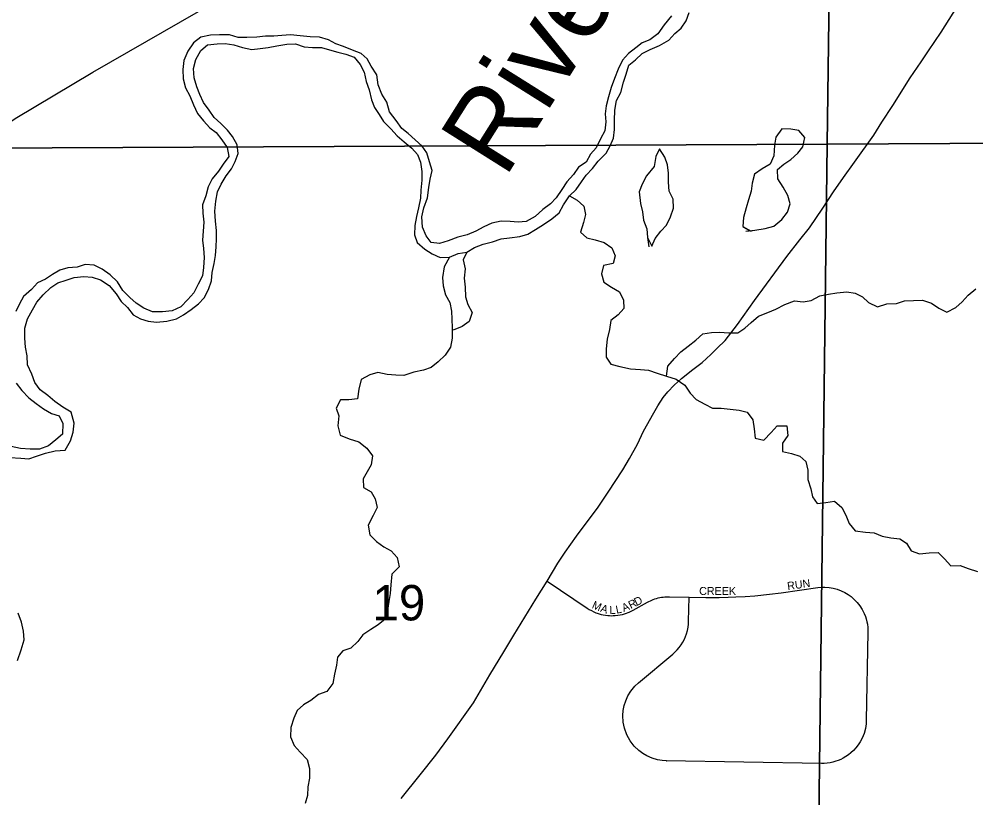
# Model space of a CAD drawing. Extents: x 1857828 to 2277390, y 930619 to 1324581.
# Drawn here: x 2065754 to 2071728, y 1200295 to 1205159 of the extents above; entities that cross this region are included whole.
import ezdxf

# ---------------------------------------------------------------- set-up
doc = ezdxf.new("R2010")
doc.units = 0
for name, color, linetype in [('GM_X_County_Road', 7, 'Continuous'), ('GM_X_Major_River', 7, 'Continuous'), ('GM_X_Major_River_Text', 7, 'Continuous'), ('GM_X_Minor_Lake', 7, 'Continuous'), ('GM_X_Minor_River', 7, 'Continuous'), ('GM_X_Section', 7, 'Continuous'), ('GM_X_Section_Text', 7, 'Continuous'), ('GM_X_Township_Subdivision', 7, 'Continuous'), ('GM_X_Township_Subdivision_Text', 7, 'Continuous'), ('GM_X_US_Route', 7, 'Continuous')]:
    doc.layers.add(name, color=color, linetype=linetype)

msp = doc.modelspace()

# ---------------------------------------------------------------- linework, layer by layer
at = {"layer": 'GM_X_County_Road'}
msp.add_lwpolyline([(2068140.2, 1200292.1), (2068258.8, 1200439.3), (2068355.7, 1200562.4), (2068430.8, 1200663.2), (2068590.7, 1200889), (2068693.1, 1201064.2), (2068779.9, 1201207.2), (2068842.9, 1201312), (2068980.9, 1201535.6), (2069051.9, 1201648.4), (2069118.9, 1201761.2), (2069164.3, 1201829.7), (2069235.3, 1201930.5), (2069369.7, 1202112), (2069432.8, 1202204.6), (2069523.6, 1202343.7), (2069565, 1202414.2), (2069616.1, 1202504.8), (2069653.4, 1202585.3), (2069716.4, 1202700), (2069742, 1202744.3), (2069775.6, 1202796.7), (2069805.2, 1202831), (2069844.8, 1202873.4), (2069890.4, 1202913.9), (2069959.9, 1202970.6), (2070019.5, 1203015.1), (2070073, 1203063.7), (2070112.6, 1203104.1), (2070162.2, 1203152.6), (2070239.3, 1203251.4), (2070345.9, 1203402.6), (2070547.4, 1203676.8), (2070628.4, 1203781.7), (2070689.8, 1203856.4), (2070772.7, 1203979.3), (2070839.7, 1204080), (2070900.9, 1204170.7), (2070970.1, 1204265.5), (2071090.5, 1204434.8), (2071141.8, 1204515.4), (2071208.8, 1204620.2), (2071317.3, 1204793.4), (2071386.4, 1204892.1), (2071431.8, 1204960.7), (2071510.7, 1205077.5), (2071636.9, 1205275)], dxfattribs=at)
at = {"layer": 'GM_X_Major_River'}
for points in [[(2068269, 1204154.3), (2068263.1, 1204090.2), (2068259.3, 1204040.1), (2068247.4, 1203979.9), (2068235.5, 1203925.8), (2068225.6, 1203869.6), (2068223.8, 1203811.5), (2068239.9, 1203763.4), (2068288, 1203723.4), (2068334.1, 1203693.4), (2068384.1, 1203671.4), (2068442.1, 1203673.5), (2068496.1, 1203695.6), (2068550.1, 1203703.7), (2068598, 1203733.8), (2068652, 1203754), (2068709.9, 1203768.1), (2068763.9, 1203786.2), (2068815.9, 1203792.3), (2068879.9, 1203802.4), (2068929.9, 1203816.5), (2068977.8, 1203844.6), (2069027.7, 1203876.8), (2069079.7, 1203912.9), (2069125.6, 1203949.1), (2069153.5, 1203999.2), (2069191.3, 1204055.4), (2069233.3, 1204095.6), (2069265.2, 1204143.7), (2069295.1, 1204183.8), (2069335, 1204226), (2069368.9, 1204272.1), (2069418.8, 1204322.3), (2069444.7, 1204368.5), (2069464.6, 1204416.6), (2069472.4, 1204470.7), (2069472.3, 1204526.9), (2069474.2, 1204591), (2069484, 1204651.2), (2069511.9, 1204701.3), (2069527.8, 1204765.5), (2069543.6, 1204815.6), (2069561.5, 1204871.8), (2069603.4, 1204905.9), (2069645.4, 1204944), (2069695.3, 1204970.2), (2069753.3, 1204994.3), (2069811.2, 1205028.5), (2069849.1, 1205068.6), (2069889, 1205102.7), (2069918.9, 1205148.9), (2069938.8, 1205201)], [(2069826.8, 1205178.8), (2069781, 1205122.6), (2069743.1, 1205068.4), (2069693.2, 1205030.3), (2069645.2, 1205012.2), (2069605.3, 1204980.1), (2069559.3, 1204943.9), (2069521.4, 1204903.8), (2069493.6, 1204847.6), (2069471.7, 1204789.4), (2069451.8, 1204731.3), (2069434, 1204673.1), (2069420.1, 1204617), (2069414.2, 1204566.9), (2069418.3, 1204516.8), (2069410.4, 1204462.6), (2069384.6, 1204412.5), (2069356.7, 1204356.3), (2069322.8, 1204316.2), (2069294.9, 1204266), (2069246.9, 1204233.9)], [(2069246.9, 1204233.9), (2069215, 1204189.8), (2069173.1, 1204143.6), (2069143.2, 1204095.4), (2069107.4, 1204043.3), (2069071.4, 1204005.1), (2069023.5, 1203971), (2068975.6, 1203926.8), (2068919.7, 1203894.7), (2068869.7, 1203890.6), (2068819.7, 1203894.5), (2068763.7, 1203896.4), (2068705.7, 1203884.3), (2068655.7, 1203862.2), (2068605.8, 1203834.1), (2068551.8, 1203812), (2068493.8, 1203797.8), (2068433.9, 1203773.7), (2068379.9, 1203757.6), (2068325.9, 1203763.5), (2068295.8, 1203805.6), (2068273.7, 1203859.7), (2068269.5, 1203923.8), (2068281.4, 1203980), (2068303.3, 1204044.1), (2068313.1, 1204108.3), (2068321, 1204160.4), (2068332.9, 1204214.6), (2068316.7, 1204268.7), (2068300.6, 1204324.8), (2068270.5, 1204366.8), (2068226.4, 1204404.8), (2068184.3, 1204444.9), (2068144.2, 1204476.9), (2068108.1, 1204527), (2068066, 1204581), (2068049.8, 1204641.1), (2068019.7, 1204691.2), (2067995.6, 1204749.3), (2067987.4, 1204811.4), (2067953.3, 1204865.5), (2067927.2, 1204911.6), (2067889.1, 1204945.6), (2067835.1, 1204965.6), (2067779, 1204987.5), (2067731, 1205005.5), (2067684.9, 1205029.5), (2067628.9, 1205047.5), (2067570.8, 1205049.4), (2067508.8, 1205055.3), (2067448.8, 1205061.2), (2067394.8, 1205057.1), (2067344.8, 1205053.1), (2067292.8, 1205053), (2067238.8, 1205046.9), (2067176.8, 1205044.8), (2067122.8, 1205044.8), (2067066.7, 1205060.7), (2067004.7, 1205060.6), (2066948.7, 1205058.5), (2066888.8, 1205046.4), (2066842.8, 1205010.3), (2066806.9, 1204960.1), (2066783.1, 1204899.9), (2066777.2, 1204843.8), (2066779.4, 1204785.7), (2066793.5, 1204729.6), (2066819.6, 1204679.5), (2066843.7, 1204623.4), (2066867.9, 1204569.3), (2066906, 1204523.3), (2066944.1, 1204481.2), (2066984.1, 1204451.2), (2067020.3, 1204405.2), (2067052.4, 1204357.1), (2067062.5, 1204301), (2067028.6, 1204252.8), (2066998.7, 1204208.7), (2066958.8, 1204162.5), (2066934.9, 1204112.4), (2066919, 1204056.2), (2066899.2, 1204000.1), (2066901.3, 1203948), (2066907.4, 1203891.8), (2066903.6, 1203835.7), (2066899.7, 1203779.6), (2066905.8, 1203727.5), (2066909.9, 1203671.3), (2066906.1, 1203607.2), (2066898.2, 1203555.1), (2066872.3, 1203504.9), (2066844.4, 1203448.8), (2066808.5, 1203408.6), (2066764.6, 1203362.4), (2066710.7, 1203338.3), (2066648.7, 1203330.2), (2066586.7, 1203330.1), (2066532.6, 1203354.1), (2066484.5, 1203386.1), (2066444.5, 1203420.1), (2066402.3, 1203464.2)], [(2066078.1, 1202704), (2066028, 1202736), (2065977.9, 1202772), (2065933.8, 1202808), (2065885.7, 1202844), (2065851.6, 1202890.1), (2065833.5, 1202942.2), (2065807.3, 1203000.3), (2065805.2, 1203056.4), (2065793.1, 1203110.5), (2065789, 1203166.6), (2065788.8, 1203228.8), (2065806.7, 1203286.9), (2065836.6, 1203343.1), (2065864.4, 1203391.2), (2065904.3, 1203437.4), (2065952.2, 1203483.6), (2065996.2, 1203511.7), (2066048.1, 1203529.8), (2066098.1, 1203545.9), (2066158.1, 1203552), (2066210.1, 1203548.1), (2066262.2, 1203530.1), (2066316.3, 1203496.1), (2066360.4, 1203444.1), (2066390.5, 1203396), (2066430.6, 1203358), (2066466.7, 1203311.9), (2066512.8, 1203287.9), (2066560.8, 1203271.9), (2066612.8, 1203266), (2066676.8, 1203272.1), (2066736.8, 1203288.2), (2066780.7, 1203312.3), (2066828.7, 1203346.5), (2066874.6, 1203380.6), (2066908.5, 1203418.8), (2066936.4, 1203470.9), (2066954.3, 1203525.1), (2066960.2, 1203577.2), (2066972, 1203633.4), (2066979.9, 1203683.5), (2066983.8, 1203737.6), (2066985.7, 1203787.7), (2066985.6, 1203839.8), (2066979.4, 1203898), (2066975.3, 1203960.1), (2066983.1, 1204022.2), (2066993, 1204080.4), (2067014.9, 1204128.5), (2067046.8, 1204180.7), (2067080.7, 1204224.8), (2067102.6, 1204271), (2067122.5, 1204319.1), (2067116.3, 1204373.2), (2067086.2, 1204425.3), (2067056.1, 1204465.4), (2067014, 1204507.4), (2066971.9, 1204545.4), (2066939.8, 1204591.5), (2066905.7, 1204637.5), (2066881.6, 1204687.6), (2066863.5, 1204735.7), (2066847.3, 1204791.8), (2066843.2, 1204851.9), (2066857.1, 1204908.1), (2066889, 1204964.2), (2066930.9, 1204998.4), (2066990.9, 1205004.5), (2067040.9, 1205006.6), (2067094.9, 1204998.6), (2067148.9, 1204982.6), (2067207, 1204968.7), (2067259, 1204976.8), (2067309, 1204982.9), (2067362.9, 1204993), (2067424.9, 1205003.1), (2067478.9, 1205005.2), (2067533, 1204987.2), (2067585, 1204981.2), (2067643, 1204981.3), (2067693, 1204967.4), (2067743.1, 1204953.4), (2067793.1, 1204941.4), (2067845.2, 1204921.5), (2067883.3, 1204875.4), (2067909.4, 1204827.4), (2067921.5, 1204769.2), (2067939.7, 1204717.2), (2067953.8, 1204655), (2067973.9, 1204606.9), (2068002, 1204562.9), (2068030.1, 1204520.8), (2068074.2, 1204474.8), (2068114.3, 1204430.8), (2068158.4, 1204392.7), (2068206.5, 1204352.7), (2068240.6, 1204314.7), (2068260.7, 1204266.6), (2068268.9, 1204208.5), (2068269, 1204154.3)], [(2066402.3, 1203464.2), (2066368.2, 1203518.2), (2066322.1, 1203562.3), (2066272, 1203598.3), (2066222, 1203622.3), (2066165.9, 1203626.2), (2066116, 1203610.1), (2066058, 1203606), (2066008, 1203591.9), (2065962.1, 1203563.8), (2065918.1, 1203535.6), (2065868.2, 1203511.5), (2065830.3, 1203471.4), (2065782.4, 1203427.2), (2065756.5, 1203381.1), (2065732.6, 1203332.9)], [(2065735.6, 1202885.9), (2065771.7, 1202839.9), (2065813.8, 1202793.8), (2065859.9, 1202757.8), (2065906, 1202725.8), (2065956.1, 1202695.8), (2066004.1, 1202681.8), (2066026.2, 1202633.7), (2066024.4, 1202567.6), (2065982.4, 1202531.4), (2065936.5, 1202493.3), (2065880.6, 1202473.2), (2065822.6, 1202473.1), (2065762.5, 1202477), (2065704.5, 1202491)], [(2065696.7, 1202420.8), (2065764.7, 1202416.9), (2065814.7, 1202412.9), (2065862.7, 1202429), (2065918.6, 1202449.2), (2065978.6, 1202463.3), (2066040.6, 1202467.4), (2066074.5, 1202525.6), (2066092.3, 1202579.7), (2066098.2, 1202635.8), (2066078.1, 1202704)], [(2065743.6, 1201153.9), (2065767.4, 1201220.1), (2065785.3, 1201282.3), (2065781.2, 1201336.4), (2065769, 1201392.5), (2065748.9, 1201448.6)]]:
    msp.add_lwpolyline(points, dxfattribs=at)
at = {"layer": 'GM_X_Minor_Lake'}
for points in [[(2070573.5, 1204472.3), (2070517.6, 1204474.6), (2070479.3, 1204422.6), (2070471.1, 1204372.6), (2070466.8, 1204306.4), (2070444.6, 1204252.4), (2070394.5, 1204224.6), (2070346.4, 1204190.7), (2070332.1, 1204134.7), (2070325.9, 1204084.6), (2070307.7, 1204030.6), (2070293.5, 1203980.5), (2070277.2, 1203920.4), (2070273, 1203864.3), (2070318.5, 1203837.7)], [(2070573.5, 1204472.3), (2070517.6, 1204474.6), (2070479.3, 1204422.6), (2070471.1, 1204372.6), (2070466.8, 1204306.4), (2070444.6, 1204252.4), (2070394.5, 1204224.6), (2070346.4, 1204190.7), (2070332.1, 1204134.7), (2070325.9, 1204084.6), (2070307.7, 1204030.6), (2070293.5, 1203980.5), (2070277.2, 1203920.4), (2070273, 1203864.3), (2070324.8, 1203834)], [(2070292.8, 1203834.2), (2070292.8, 1203834.2), (2070348.9, 1203841.9), (2070412.9, 1203851.7), (2070467, 1203865.4), (2070517.2, 1203907.3), (2070551.3, 1203953.2), (2070567.6, 1204005.3), (2070553.8, 1204057.5), (2070524, 1204109.7), (2070492.2, 1204162), (2070490.5, 1204220.1), (2070528.6, 1204254), (2070572.7, 1204281.9), (2070616.9, 1204321.8), (2070647.1, 1204361.7), (2070659.3, 1204419.8), (2070623.5, 1204464.1), (2070573.5, 1204472.3)], [(2070318.5, 1203837.7), (2070348.9, 1203841.9), (2070412.9, 1203851.7), (2070467, 1203865.4), (2070517.2, 1203907.3), (2070551.3, 1203953.2), (2070567.6, 1204005.3), (2070553.8, 1204057.5), (2070524, 1204109.7), (2070492.2, 1204162), (2070490.5, 1204220.1), (2070528.6, 1204254), (2070572.7, 1204281.9), (2070616.9, 1204321.8), (2070647.1, 1204361.7), (2070659.3, 1204419.8), (2070623.5, 1204464.1), (2070573.5, 1204472.3)], [(2069753, 1204349.8), (2069728.8, 1204301.8), (2069718.5, 1204239.8), (2069672.3, 1204179.8), (2069644.1, 1204127.8), (2069625.9, 1204079.8), (2069633.6, 1204007.6), (2069647.3, 1203955.4), (2069653.1, 1203903.3), (2069672.9, 1203849.1), (2069678.7, 1203794.9), (2069704.4, 1203740.7)], [(2069753, 1204349.8), (2069728.8, 1204301.8), (2069718.5, 1204239.8), (2069672.3, 1204179.8), (2069644.1, 1204127.8), (2069625.9, 1204079.8), (2069633.6, 1204007.6), (2069647.3, 1203955.4), (2069653.1, 1203903.3), (2069672.9, 1203849.1), (2069678.7, 1203794.9), (2069686.4, 1203736.8)], [(2069704.4, 1203740.7), (2069724.6, 1203788.7), (2069760.8, 1203834.6), (2069797, 1203872.6), (2069821.2, 1203924.6), (2069839.4, 1203978.6), (2069837.7, 1204034.7), (2069813.9, 1204085), (2069808.1, 1204141.1), (2069808.4, 1204197.2), (2069802.6, 1204249.4), (2069786.8, 1204297.6), (2069753, 1204349.8)]]:
    msp.add_lwpolyline(points, dxfattribs=at)
at = {"layer": 'GM_X_Minor_River'}
for points in [[(2069191.3, 1204055.4), (2069239.4, 1204029.4), (2069279.5, 1203991.4), (2069291.6, 1203939.3), (2069277.7, 1203889.2), (2069259.9, 1203829), (2069298, 1203793), (2069352, 1203781), (2069408, 1203765.1), (2069454.1, 1203731), (2069476.2, 1203680.9), (2069462.4, 1203632.8), (2069402.4, 1203620.7), (2069390.5, 1203568.6), (2069404.6, 1203516.5), (2069452.7, 1203484.5), (2069502.8, 1203456.5), (2069526.9, 1203404.4), (2069531, 1203352.3), (2069495.1, 1203312.1), (2069449.2, 1203278), (2069441.3, 1203219.8), (2069425.4, 1203159.7), (2069419.6, 1203099.6), (2069419.7, 1203047.4), (2069447.8, 1203003.4), (2069505.8, 1202989.4), (2069571.9, 1202975.5), (2069633.9, 1202971.6), (2069683.9, 1202967.6), (2069738, 1202947.6), (2069796, 1202929.7), (2069856.1, 1202909.7), (2069910.2, 1202873.7), (2069944.3, 1202823.6), (2069982.4, 1202783.6), (2070036.4, 1202753.6), (2070084.5, 1202729.6), (2070138.5, 1202729.7), (2070194.5, 1202723.8), (2070250.6, 1202717.8), (2070300.6, 1202703.9), (2070334.7, 1202655.8), (2070342.8, 1202599.7), (2070351, 1202541.6), (2070405, 1202529.6), (2070450.9, 1202577.8), (2070486.8, 1202619.9), (2070546.8, 1202620), (2070553, 1202557.9), (2070521.1, 1202511.7), (2070521.2, 1202459.6), (2070577.2, 1202445.6), (2070629.3, 1202429.7), (2070667.3, 1202395.7), (2070679.5, 1202341.6), (2070679.6, 1202283.4), (2070697.7, 1202225.3), (2070707.9, 1202175.2), (2070738, 1202133.1), (2070792, 1202139.2), (2070845.9, 1202149.3), (2070892, 1202109.3), (2070916.2, 1202061.2), (2070936.3, 1202009.1), (2070974.4, 1201963.1), (2071038.4, 1201955.1), (2071092.4, 1201951.2), (2071142.5, 1201929.2), (2071196.5, 1201919.3), (2071252.5, 1201913.4), (2071294.6, 1201885.3), (2071324.7, 1201839.3), (2071376.8, 1201819.3), (2071436.8, 1201825.4), (2071492.8, 1201827.5), (2071532.9, 1201787.4), (2071571, 1201745.4)], [(2068442.1, 1203673.5), (2068408.3, 1203611.3), (2068398.4, 1203545.1), (2068402.5, 1203493), (2068416.7, 1203436.9), (2068442.8, 1203388.8), (2068452.9, 1203334.7), (2068457, 1203284.6), (2068457.1, 1203230.5), (2068457.3, 1203166.4), (2068447.4, 1203110.2), (2068413.5, 1203060.1), (2068371.6, 1203017.9), (2068327.7, 1202983.8), (2068279.7, 1202967.7), (2068217.8, 1202953.5), (2068155.8, 1202933.4), (2068105.8, 1202935.3), (2068051.8, 1202939.3), (2067993.7, 1202951.2), (2067943.8, 1202937.1), (2067889.8, 1202909), (2067875.9, 1202848.8), (2067866.1, 1202788.7), (2067812.1, 1202780.6), (2067760.1, 1202782.5), (2067734.2, 1202730.3), (2067750.3, 1202682.3), (2067744.5, 1202620.1), (2067758.6, 1202560), (2067814.7, 1202538), (2067874.7, 1202520.1), (2067924.8, 1202480), (2067960.9, 1202432), (2067953, 1202375.8), (2067927.1, 1202331.7), (2067903.2, 1202287.6), (2067905.4, 1202233.4), (2067951.4, 1202207.4), (2067977.5, 1202163.4), (2067989.7, 1202109.3), (2067963.8, 1202059.1), (2067933.9, 1201998.9), (2067944, 1201938.8), (2067986.2, 1201896.8), (2068032.2, 1201862.8), (2068076.3, 1201838.8), (2068114.4, 1201796.7), (2068126.5, 1201738.6), (2068080.6, 1201692.4), (2068074.8, 1201626.3), (2068070.9, 1201572.1), (2068063, 1201522), (2068055.1, 1201467.9), (2068039.3, 1201411.7), (2067995.4, 1201375.6), (2067949.4, 1201347.4), (2067899.5, 1201313.3), (2067869.6, 1201271.1), (2067825.7, 1201231), (2067775.7, 1201212.9), (2067741.8, 1201174.8), (2067735.9, 1201124.6), (2067724, 1201068.5), (2067712.2, 1201010.3), (2067676.3, 1200960.2), (2067624.3, 1200942), (2067576.4, 1200903.9), (2067530.4, 1200875.8), (2067490.5, 1200841.6), (2067468.6, 1200793.5), (2067450.7, 1200735.3), (2067448.9, 1200677.2), (2067471, 1200623.1), (2067509.1, 1200581), (2067553.2, 1200535), (2067567.3, 1200478.9), (2067567.5, 1200418.7), (2067557.6, 1200364.6), (2067555.7, 1200310.5), (2067539.9, 1200260.3)], [(2068550.1, 1203703.7), (2068526.2, 1203655.6), (2068538.3, 1203599.5), (2068532.4, 1203541.3), (2068538.6, 1203485.2), (2068540.7, 1203425.1), (2068556.8, 1203377), (2068582.9, 1203326.9), (2068565.1, 1203270.8), (2068521.1, 1203238.6), (2068465.2, 1203216.5)], [(2071547.3, 1203329), (2071602.5, 1203357.4), (2071642.5, 1203393.8), (2071680.4, 1203436.2), (2071728.3, 1203474.6)], [(2069796, 1202929.7), (2069803.9, 1202991.8), (2069845.8, 1203040), (2069885.7, 1203082.2), (2069931.6, 1203116.3), (2069979.5, 1203154.4), (2070023.4, 1203194.6), (2070077.4, 1203202.7), (2070127.4, 1203204.8), (2070185.4, 1203200.8), (2070241.4, 1203200.9), (2070285.4, 1203229.1), (2070325.3, 1203265.2), (2070371.2, 1203303.3), (2070429.2, 1203327.5), (2070479.1, 1203347.6), (2070535.1, 1203377.7), (2070595, 1203399.9), (2070649.1, 1203393.9), (2070699, 1203402), (2070753, 1203430.1), (2070807, 1203442.3), (2070860.9, 1203450.4), (2070923, 1203456.4), (2070975, 1203448.5), (2071021, 1203424.5), (2071057.1, 1203388.5), (2071113.2, 1203362.5), (2071173.2, 1203380.6), (2071233.2, 1203382.7), (2071283.1, 1203398.8), (2071339.1, 1203402.9), (2071395.1, 1203403), (2071451.2, 1203385), (2071497.3, 1203353), (2071547.3, 1203329)], [(2071571, 1201745.4), (2071630.4, 1201746.8), (2071680.6, 1201729), (2071738.9, 1201709.2)]]:
    msp.add_lwpolyline(points, dxfattribs=at)
at = {"layer": 'GM_X_Section'}
for points in [[(2065593.7, 1209968.9), (2070874.1, 1209998.9), (2070799.7, 1204378.1), (2065519.4, 1204352.4)], [(2070874.1, 1209998.9), (2076246.6, 1210012.2), (2076168.5, 1204407.7), (2070799.7, 1204378.1)], [(2070799.7, 1204378.1), (2070731.6, 1198809.7), (2065488.8, 1198768.7), (2065519.4, 1204352.4)], [(2076168.5, 1204407.7), (2076109.5, 1198829.7), (2070731.6, 1198809.7), (2070799.7, 1204378.1)]]:
    msp.add_lwpolyline(points, close=True, dxfattribs=at)
at = {"layer": 'GM_X_Township_Subdivision'}
msp.add_lwpolyline([(2069051.9, 1201648.4), (2069300.7, 1201480.5), (2069313.4, 1201472.4), (2069327.1, 1201464.8), (2069343.2, 1201457), (2069355.3, 1201452), (2069364.3, 1201448.7), (2069376.4, 1201444.8), (2069389.4, 1201441.3), (2069401.9, 1201438.5), (2069416.4, 1201436.1), (2069429.5, 1201434.6), (2069440.9, 1201433.8), (2069452.4, 1201433.4), (2069463.8, 1201433.6), (2069476.9, 1201434.3), (2069491.8, 1201436), (2069506.6, 1201438.4), (2069520.8, 1201441.5), (2069539.5, 1201446.9), (2069563.5, 1201455.9), (2069588, 1201467.9), (2069677.2, 1201517.4), (2069685.8, 1201521.9), (2069696.3, 1201527), (2069705.3, 1201530.9), (2069712.4, 1201533.8), (2069723.9, 1201537.9), (2069733.8, 1201540.9), (2069744.5, 1201543.8), (2069754.9, 1201546.2), (2069765.4, 1201548.1), (2069775.9, 1201549.7), (2069785.2, 1201550.7), (2069800.2, 1201551.7), (2069815.4, 1201551.8), (2069937.4, 1201549.7), (2070042.5, 1201547.8), (2070077.8, 1201547.4), (2070125.2, 1201547.5), (2070180.8, 1201548.5), (2070229.8, 1201550.4), (2070286.9, 1201553.5), (2070347.7, 1201558), (2070439.5, 1201567.1), (2070512.6, 1201576.5), (2070740.5, 1201608.5), (2070763.9, 1201610.7), (2070785.1, 1201611), (2070812.3, 1201609.1), (2070837.7, 1201604.7), (2070862.5, 1201598.1), (2070887.2, 1201588.9), (2070910.9, 1201577.3), (2070930.1, 1201565.8), (2070948.7, 1201552.4), (2070968.8, 1201535), (2070987.6, 1201515.1), (2071003.3, 1201495), (2071017.8, 1201472.3), (2071030.4, 1201447.2), (2071038.3, 1201427.5), (2071042.7, 1201413.6), (2071047.3, 1201395.7), (2071050.5, 1201379.4), (2071052.9, 1201359.6), (2071053.9, 1201331.1), (2071044.2, 1200780.9), (2071042.7, 1200757.2), (2071038.2, 1200728.3), (2071030, 1200698.3), (2071018.4, 1200669.3), (2071006.2, 1200646.1), (2070993.5, 1200626.6), (2070979.4, 1200608.4), (2070964, 1200591.5), (2070947.9, 1200576.6), (2070933, 1200564.8), (2070915.5, 1200552.8), (2070900.1, 1200543.8), (2070884.1, 1200535.8), (2070869.1, 1200529.4), (2070853.3, 1200523.8), (2070835.9, 1200518.8), (2070817.6, 1200514.9), (2070799.7, 1200512.3), (2070780, 1200510.8), (2070764.2, 1200510.6), (2069793.9, 1200527.7), (2069795.6, 1200526.3), (2069769.2, 1200529.3), (2069740.5, 1200533.9), (2069707.9, 1200543.1), (2069673.9, 1200557.6), (2069648.8, 1200572.1), (2069623.8, 1200590.4), (2069594.6, 1200618.3), (2069568.9, 1200651.6), (2069548.3, 1200688.9), (2069533.3, 1200730.3), (2069525.7, 1200768.4), (2069523.6, 1200809.7), (2069526.2, 1200841), (2069532.6, 1200872.8), (2069541.6, 1200900.8), (2069555.9, 1200932.2), (2069574.2, 1200961.9), (2069599.5, 1200992.6), (2069621.9, 1201013.6), (2069836.5, 1201193.7), (2069849.2, 1201205), (2069864, 1201220.2), (2069875.7, 1201234.1), (2069887.9, 1201250.8), (2069898.6, 1201268.1), (2069908.1, 1201286.3), (2069915.4, 1201302.9), (2069921.5, 1201320), (2069927.3, 1201340.5), (2069931.4, 1201361), (2069933.8, 1201381), (2069934.8, 1201399.7), (2069937.4, 1201549.7)], dxfattribs=at)
at = {"layer": 'GM_X_US_Route'}
msp.add_lwpolyline([(2054677.9, 1195170.3), (2054837.4, 1195352.9), (2055032, 1195549.7), (2055173.6, 1195679.7), (2055317.8, 1195799.7), (2056203.6, 1196482.3), (2056601.3, 1196831.2), (2057041, 1197329.5), (2057849.7, 1198281.9), (2058613.4, 1199064.3), (2059059.7, 1199476.8), (2059264.5, 1199666), (2059500.2, 1199857.9), (2059938.7, 1200214.7), (2060131.4, 1200354.4), (2065339.2, 1204278.5), (2065730.3, 1204538.2), (2066214.7, 1204827.1), (2069304.1, 1206604.3)], dxfattribs=at)

# ---------------------------------------------------------------- texts
at = {"layer": 'GM_X_Major_River_Text'}
msp.add_text('River', height=500.24, rotation=57.81943, dxfattribs=at).set_placement((2068787.1, 1204159.1))
at = {"layer": 'GM_X_Section_Text'}
msp.add_text('19', height=221, rotation=0.00001, dxfattribs=at).set_placement((2067960.9, 1201403.9))
at = {"layer": 'GM_X_Township_Subdivision_Text'}
for s, rotation, p in [('RUN', 7.85663, (2070553.4, 1201593.3)), ('CREEK', 0.00001, (2070000.3, 1201562.6)), ('M', 336.09114, (2069326.6, 1201482.6)), ('A', 341.79961, (2069379.9, 1201459.2)), ('A', 22.80336, (2069529.6, 1201455.5)), ('R', 26.62418, (2069573.4, 1201474.1)), ('D', 27.44653, (2069609.5, 1201492.2)), ('L', 2.7786, (2069441.4, 1201442.8)), ('L', 11.16646, (2069484.5, 1201445.5))]:
    msp.add_text(s, height=50, rotation=rotation, dxfattribs=at).set_placement(p)

doc.saveas('drawing.dxf')
